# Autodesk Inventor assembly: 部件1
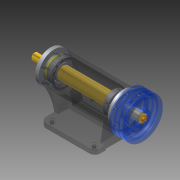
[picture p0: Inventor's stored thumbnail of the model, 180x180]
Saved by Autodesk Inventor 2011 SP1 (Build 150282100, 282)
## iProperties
Created: 2014-03
Part Number: 部件1
Document SubType Name: Assembly
Designer: Administrator
Author: Administrator
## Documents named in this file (11)
- E:\寒假作业\部件1.iam
- E:\寒假作业\6-6座体.ipt
- E:\寒假作业\6-6滚动轴承 30307 GB_T 297-94.ipt
- E:\寒假作业\装配图\p78  2.ipt
- E:\寒假作业\装配图\p792.ipt
- E:\寒假作业\6-6螺钉 GB_T 70.1 M8 x 16.ipt
- E:\寒假作业\6-6键GB_T 1096 - A 8 x 7 x 40.ipt
- E:\寒假作业\装配图\p77.ipt
- E:\寒假作业\6-6螺钉 GB_T 70.1 M8 x 16 - 副本.ipt
- E:\寒假作业\6-6带轮.ipt
- E:\寒假作业\6-6销GB_T 119.1-2000 Type B 3 h8 x 12.ipt
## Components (23 placed, 10 different names)
1. 6-6座体:1 — 插入:4, 插入:18
2. 6-6滚动轴承 30307 GB_T 297-94:1 — 配合:6, 配合:10
3. 6-6滚动轴承 30307 GB_T 297-94:2 — 配合:5, 配合:9
4. p78  2:1 — 配合:3, 配合:4, 配合:9
5. p792:2 — 插入:4, 配合:2, 插入:6, 插入:7, 插入:8, 插入:9, 插入:10, 配合:3, 配合:4, 配合:8
6. 6-6螺钉 GB_T 70.1 M8 x 16:1 — 插入:9
7. 6-6螺钉 GB_T 70.1 M8 x 16:2 — 插入:7
8. 6-6螺钉 GB_T 70.1 M8 x 16:3 — 插入:6
9. 6-6螺钉 GB_T 70.1 M8 x 16:4 — 配合:2
10. 6-6螺钉 GB_T 70.1 M8 x 16:5 — 插入:10
11. 6-6螺钉 GB_T 70.1 M8 x 16:6 — 插入:8
12. 6-6键GB_T 1096 - A 8 x 7 x 40:1 — 配合:11, 相切:1, 配合:12, 配合:14
13. p77:1 — 配合:5, 配合:6, 配合:7, 配合:8, 配合:10, 配合:11, 相切:1, 配合:12, 配合:13, 配合:15, 配合:16, 表面齐平:1, 配合:17, 配合:18
14. p792:3 — 插入:18, 插入:19, 插入:20, 插入:21, 插入:22, 插入:23, 插入:24, 配合:7
15. 6-6螺钉 GB_T 70.1 M8 x 16:7 — 插入:24
16. 6-6螺钉 GB_T 70.1 M8 x 16:8 — 插入:23
17. 6-6螺钉 GB_T 70.1 M8 x 16:9 — 插入:21
18. 6-6螺钉 GB_T 70.1 M8 x 16:10 — 插入:20
19. 6-6螺钉 GB_T 70.1 M8 x 16:11 — 插入:19
20. 6-6螺钉 GB_T 70.1 M8 x 16:12 — 插入:22
21. 6-6螺钉 GB_T 70.1 M8 x 16 - 副本:1 — 配合:17, 配合:18
22. 6-6带轮:1 — 配合:13, 配合:14, 配合:15
23. 6-6销GB_T 119.1-2000 Type B 3 h8 x 12:1 — 配合:16, 表面齐平:1
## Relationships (32: Mate 17, Insert 13, Tangent 1, Flush 1)
- 插入:4 [Insert]: 6-6座体:1 ↔ p792:2
- 配合:2 [Mate]: p792:2 ↔ 6-6螺钉 GB_T 70.1 M8 x 16:4
- 插入:6 [Insert]: p792:2 ↔ 6-6螺钉 GB_T 70.1 M8 x 16:3
- 插入:7 [Insert]: p792:2 ↔ 6-6螺钉 GB_T 70.1 M8 x 16:2
- 插入:8 [Insert]: p792:2 ↔ 6-6螺钉 GB_T 70.1 M8 x 16:6
- 插入:9 [Insert]: p792:2 ↔ 6-6螺钉 GB_T 70.1 M8 x 16:1
- 插入:10 [Insert]: p792:2 ↔ 6-6螺钉 GB_T 70.1 M8 x 16:5
- 插入:18 [Insert]: 6-6座体:1 ↔ p792:3
- 插入:19 [Insert]: p792:3 ↔ 6-6螺钉 GB_T 70.1 M8 x 16:11
- 插入:20 [Insert]: p792:3 ↔ 6-6螺钉 GB_T 70.1 M8 x 16:10
- 插入:21 [Insert]: p792:3 ↔ 6-6螺钉 GB_T 70.1 M8 x 16:9
- 插入:22 [Insert]: p792:3 ↔ 6-6螺钉 GB_T 70.1 M8 x 16:12
- 插入:23 [Insert]: p792:3 ↔ 6-6螺钉 GB_T 70.1 M8 x 16:8
- 插入:24 [Insert]: p792:3 ↔ 6-6螺钉 GB_T 70.1 M8 x 16:7
- 配合:3 [Mate]: p78  2:1 ↔ p792:2
- 配合:4 [Mate]: p78  2:1 ↔ p792:2
- 配合:5 [Mate]: 6-6滚动轴承 30307 GB_T 297-94:2 ↔ p77:1
- 配合:6 [Mate]: 6-6滚动轴承 30307 GB_T 297-94:1 ↔ p77:1
- 配合:7 [Mate]: p77:1 ↔ p792:3
- 配合:8 [Mate]: p792:2 ↔ p77:1
- 配合:9 [Mate]: 6-6滚动轴承 30307 GB_T 297-94:2 ↔ p78  2:1
- 配合:10 [Mate]: 6-6滚动轴承 30307 GB_T 297-94:1 ↔ p77:1
- 配合:11 [Mate]: 6-6键GB_T 1096 - A 8 x 7 x 40:1 ↔ p77:1
- 相切:1 [Tangent]: 6-6键GB_T 1096 - A 8 x 7 x 40:1 ↔ p77:1
- 配合:12 [Mate]: 6-6键GB_T 1096 - A 8 x 7 x 40:1 ↔ p77:1
- 配合:13 [Mate]: p77:1 ↔ 6-6带轮:1
- 配合:14 [Mate]: 6-6键GB_T 1096 - A 8 x 7 x 40:1 ↔ 6-6带轮:1
- 配合:15 [Mate]: p77:1 ↔ 6-6带轮:1
- 配合:16 [Mate]: p77:1 ↔ 6-6销GB_T 119.1-2000 Type B 3 h8 x 12:1
- 表面齐平:1 [Flush]: p77:1 ↔ 6-6销GB_T 119.1-2000 Type B 3 h8 x 12:1
- 配合:17 [Mate]: p77:1 ↔ 6-6螺钉 GB_T 70.1 M8 x 16 - 副本:1
- 配合:18 [Mate]: p77:1 ↔ 6-6螺钉 GB_T 70.1 M8 x 16 - 副本:1
